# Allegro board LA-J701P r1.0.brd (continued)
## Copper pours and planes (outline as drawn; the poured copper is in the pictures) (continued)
LX1_CPU on BOTTOM: 97.62,103.55 98.5,103.55 98.66,103.4 98.66,102.74 98.81,102.58 98.81,101.29 98.63,101.11 98.63,100.88 98.5,100.75 98.5,99.61 98.43,99.54 98.3,99.54 98.23,99.61 98.23,100.45 98.24,100.46 98.24,100.83 98.38,100.97 98.38,102.18 97.87,102.68 97.69,102.68 97.59,102.79 97.59,103.52
LX1_CPU on IN3: 99.38,104.18 99.64,103.93 99.64,103.43 99.05,102.85 99.05,102.65 98.78,102.38 98.78,101.59 98.66,101.47 98.5,101.47 98.35,101.62 98.35,102.99 98.58,103.22 98.58,104.03 98.73,104.18
LX1_CPU on IN3: 129.34,103.46 130.1,103.46 130.25,103.31 130.25,102.24 130.25,102.23 130.25,101.94 130.06,101.76 129.37,101.76 129.09,102.04 129.09,103.21
LX1_NB on TOP (solid shape): 82.54,99.55 82.54,96.93 82.41,96.8 81.14,96.8 81.04,96.91 81.04,99.6 81.12,99.67 82.41,99.67
LX1_NB on BOTTOM (solid shape): 81.61,104.64 81.61,100.17 83.32,98.47 83.32,95.32 82.93,94.94 81.72,94.94 81.64,95.01 81.64,96.73 80.67,96.73 80.67,95.04 80.57,94.94 78.95,94.94 78.79,95.09 78.79,104.23 79.51,104.95 81.31,104.95
LX1_NB on BOTTOM: 94.85,103.52 95.67,103.52 95.79,103.4 95.79,102.73 96.12,102.41 96.12,102.2 96.33,101.99 96.38,101.99 96.5,101.87 96.5,101.72 96.88,101.34 96.88,99.59 96.82,99.52 96.75,99.52 96.63,99.65 96.63,100.35 96.58,100.39 96.58,101.22 96.28,101.52 96.16,101.52 96.04,101.64 96.04,101.76 95.83,101.97 95.64,101.97 94.72,102.89 94.72,103.4
LX1_NB on IN3: 94.72,103.45 95.51,103.45 95.99,102.96 95.99,102.43 96.5,101.92 96.5,101.67 96.32,101.49 96.22,101.49 94.67,103.04 94.67,103.4
LX1_NB on IN3: 81.09,105.76 81.54,105.76 81.92,105.38 81.92,105.15 81.16,104.39 80.19,104.39 80.08,104.5 80.08,104.74
LX2_CHG on TOP (solid shape): 68.35,11.79 68.35,7.92 68.61,7.66 69.27,7.66 69.35,7.59 69.35,4.13 69.27,4.06 67.36,4.06 67.19,4.23 67.19,5.77 66.95,6.01 65.43,6.01 65.31,6.14 65.31,7.61 65.33,7.63 65.33,12.06 65.65,12.38 67.77,12.38
LX2_CHG on BOTTOM (solid shape): 70.89,11.76 70.89,7.66 69.14,5.91 65.48,5.91 65.31,6.09 65.31,11.42 65.5,11.61 66.89,11.61 67.08,11.8 70.86,11.8
LX2_CHG on BOTTOM (solid shape): 45.04,10.12 45.04,9.36 45.91,8.49 46.73,8.49 46.78,8.44 46.78,8.34 46.73,8.29 45.86,8.29 45.81,8.23 45.26,8.23 44.08,9.41 44.08,10.21 44.13,10.26 44.9,10.26
LX2_CHG on IN3 (solid shape): 67.12,13.42 67.12,12.01 66.95,11.83 66.15,11.83 65.9,12.08 65.9,13.57 66.18,13.85 66.69,13.85
LX2_CHG on IN3 (solid shape): 44.99,10.68 44.99,9.49 45.04,9.43 45.04,9.36 45.52,8.88 45.52,8.52 45.4,8.4 45.39,8.4 44.99,8.4 44.91,8.48 44.87,8.48 44.8,8.5 44.72,8.5 44.19,9.04 44.19,10.82 44.21,10.85 44.82,10.85
LX2_CPU on BOTTOM (solid shape): 117.53,101.72 117.53,94.96 116.01,93.44 113.8,93.44 113.69,93.34 113.69,92.65 113.87,92.47 115.5,92.47 115.78,92.19 115.78,90.52 115.45,90.19 112.91,90.19 112.35,90.75 112.35,95.12 114.86,97.63 114.86,101.62 115.12,101.87 117.38,101.87
LX2_CPU on IN3 (solid shape): 114.14,97.38 114.14,95.45 114.01,95.32 113.3,95.32 113.15,95.47 113.15,97.4 113.3,97.55 113.96,97.55
LX2_CPU on TOP: 115.05,96.58 116.55,96.58 116.75,96.37 116.75,95.05 116.5,94.8 115.05,94.8 114.93,94.93 114.93,96.45
LX2_CPU on BOTTOM: 101.5,103.28 101.5,101.08 100.07,99.65 100.07,99.62 100,99.56 99.93,99.56 99.85,99.64 99.85,100.32 99.93,100.4 100.1,100.4 100.82,101.11 100.82,101.14 100.89,101.21 100.89,101.62 100.38,102.13 100.38,103.24 100.5,103.36 101.43,103.36
LX2_CPU on IN3: 101.32,100.83 100.82,100.32 100.54,100.32 100.38,100.48 100.38,100.65 101.32,101.59 101.5,101.59 102.11,102.2 102.67,102.2 102.8,102.08 102.8,101.49 102.14,100.83
LX3_CPU on TOP (solid shape): 145.66,96.07 145.66,94.52 145.51,94.37 143.42,94.37 143.25,94.54 143.25,95.94 143.48,96.17 145.56,96.17
LX3_CPU on TOP (solid shape): 145.09,104.69 145.09,104.56 145.04,104.51 145.04,104.29 145.24,104.08 145.95,104.08 146.05,103.98 146.05,103.9 145.98,103.83 144.61,103.83 144.48,103.95 144.48,104.74 144.61,104.87 144.91,104.87
LX3_CPU on BOTTOM (solid shape): 145.93,105.15 145.93,104.01 145.77,103.85 144.76,103.85 144.63,103.98 144.63,104.89 144.96,105.22 145.85,105.22
LX3_CPU on BOTTOM (solid shape): 148.11,101.67 148.11,97.71 148.67,97.15 148.67,94.07 148.42,93.82 146.74,93.82 146.28,94.28 146.28,95.24 146.18,95.34 145.34,95.34 145.29,95.29 145.29,94.13 144.96,93.79 143.39,93.79 142.95,94.23 142.95,96.39 143.84,97.27 144.81,97.27 145.37,97.83 145.37,101.85 147.93,101.85
LX3_CPU on IN3 (solid shape): 146.21,98.09 146.21,97.4 145.95,97.15 144.94,97.15 144.75,97.34 144.75,98.13 144.91,98.29 146,98.29
LX3_CPU on IN3 (solid shape): 145.98,104.74 145.98,104.72 146.16,104.54 146.16,103.8 146.08,103.73 144.78,103.73 144.53,103.98 144.53,104.62 144.76,104.84 145.88,104.84
LX_1.8V on TOP (solid shape): 170.81,82.12 170.81,81.41 169.92,80.52 169.66,80.52 167.52,78.38 167.36,78.38 166.72,79.02 166.72,79.23 170.02,82.53 170.4,82.53
LX_1.8V on BOTTOM (solid shape): 170.98,81.92 170.98,81.26 170.17,80.45 170.12,80.45 170.02,80.55 170.02,80.75 170.17,80.9 170.17,82.35 170.25,82.43 170.48,82.43
LX_1.8V on BOTTOM (solid shape): 166.13,80.02 166.34,80.02 166.79,80.47 166.92,80.47 167.2,80.19 167.2,79.69 167.57,79.32 168.81,79.32 169.14,78.99 169.14,78.76 168.08,77.69 168.08,77.68 168.04,77.64 168.04,76.87 167.36,76.19 166.75,76.19 164.7,78.25 164.7,78.57 165.29,79.16 165.29,79.74 164.84,80.19 164.84,80.5 165.09,80.75 165.4,80.75
LX_3V on TOP (solid shape): 175.75,66.57 175.75,66.48 178.48,63.74 178.69,63.74 179.06,64.11 179.29,64.11 179.59,63.81 179.59,63.56 177.52,61.49 176.57,61.49 174.67,63.39 174.67,66.5 175.17,67.01 175.3,67.01
LX_3V on BOTTOM (solid shape): 178.81,67.97 178.81,67.72 180.11,66.41 180.11,65.45 179.18,64.51 179.18,63.82 178.04,62.69 177.49,62.69 175.59,64.58 175.59,64.74 175.03,65.3 175.03,65.63 177.83,68.42 178.36,68.42
LX_3V on TOP: 177.44,68.59 177.79,68.59 178.08,68.29 178.51,68.29 178.65,68.15 178.65,67.95 178.53,67.82 177.21,67.82 177.18,67.85 176.93,67.85 176.85,67.92 176.85,68
LX_5V on TOP (solid shape): 31.61,12.98 32.31,12.98 32.41,12.88 32.41,12.03 32.38,11.99 31.06,11.99 30.34,12.71 30.34,13.57 30.52,13.75 30.85,13.75
LX_5V on BOTTOM (solid shape): 33.96,17.1 34.6,17.1 34.65,17.05 34.65,15.13 34.8,14.98 34.98,14.98 35.08,14.88 37.34,14.88 37.42,14.95 38.13,14.95 38.22,14.86 38.22,14.74 38.15,14.67 37.37,14.67 37.24,14.55 35.33,14.55 35.03,14.24 34.12,14.24 33.39,13.52 33.39,12.83 33.18,12.62 30.69,12.62 30.28,13.02 30.28,14.98 30.99,15.69 30.99,17.11 31.35,17.47 33.6,17.47
LX_DDR on TOP (solid shape): 152.44,41.8 152.44,38.63 152.31,38.5 151.3,38.5 151.11,38.69 151.11,41.74 151.3,41.93 152.31,41.93
LX_DDR on BOTTOM (solid shape): 153.39,42.03 153.65,42.03 153.76,41.92 153.76,41.71 153.74,41.69 153.74,39.93 155.03,38.64 155.03,36.58 154.92,36.47 154.54,36.47 154.22,36.15 152.01,36.15 151.4,36.76 151.4,38.23 150.71,38.92 147.9,38.92 146.96,39.86 146.96,41.13 147.77,41.94 151.65,41.94 151.76,42.04 153.38,42.04
LX_DDR on TOP: 157.93,52.13 158.64,52.13 158.74,52.02 158.74,51.14 158.59,50.98 158.59,50.02 158.44,49.87 157.78,49.87 157.57,50.07 157.57,51.77
LX_DDR on TOP: 152.01,41.89 154.32,41.89 154.6,41.61 154.6,41 154.4,40.8 152.01,40.8 151.86,40.95 151.86,41.74
LX_DDR on BOTTOM: 160.16,54.26 160.21,54.21 160.21,54.13 160.14,54.06 159.53,54.06 158.84,53.37 158.84,51.29 158.64,51.08 158.28,51.08 158.13,51.24 158.13,52.66 158.16,52.68 158.16,53.29 159.12,54.26
LX_VDDP on TOP (solid shape): 161.61,94.29 161.61,94.09 158.94,91.42 158.94,91.32 158.18,90.56 158.08,90.56 157.42,91.22 157.42,91.5 160.65,94.72 161.18,94.72
LX_VDDP on BOTTOM (solid shape): 161.64,94.29 161.64,93.76 160.95,93.07 160.85,93.07 160.75,93.17 160.75,93.58 160.65,93.68 160.65,94.01 161.1,94.47 161.46,94.47
LX_VDDP on BOTTOM (solid shape): 156.95,91.69 158.7,91.69 158.83,91.56 159.19,91.56 159.58,91.17 159.58,91.06 156.54,88.03 156.14,88.03 152.4,91.76 152.4,93.08 153.47,94.15 154.49,94.15
M_BATA on BOTTOM: 80.74,14.76 80.99,14.51 80.99,9.53 80.59,9.12 77.54,9.12 76.19,10.47 73.8,10.47 73.3,10.98 73.3,14.36 73.7,14.76
M_VMB on BOTTOM (solid shape): outline of 91 points within 71.99,4.82 77.45,10.11
Net_14 on BOTTOM (solid shape): 178.53,92.82 170.53,92.82 170.53,100.82 178.53,100.82
REGN on BOTTOM (solid shape): 48.34,12.16 48.34,11.54 48.1,11.3 48.1,11.19 48.08,11.17 48.08,10.27 48.28,10.07 48.28,9.07 48.23,9.02 48.1,9.02 48.05,9.07 48.05,9.84 47.7,10.18 47.7,12.12 47.79,12.21 48.29,12.21
S0I3_EC#_5VEN2 on BOTTOM: 18.65,21.11 18.71,21.05 18.71,20.22 18.58,20.1 16.76,20.1 16.46,20.4 16.46,21.08 16.48,21.11
SNB_APU on TOP (solid shape): 119.1,96.18 120.02,96.18 120.07,96.13 120.07,95.04 119.71,94.68 117.63,94.68 117.43,94.89 117.43,96.49 117.5,96.56 118.72,96.56
SNB_APU2 on TOP (solid shape): 131.19,97.4 131.19,95.88 131.07,95.75 129.21,95.75 129.11,95.85 129.11,96.46 130.13,97.48 131.12,97.48
SNB_APU3 on TOP (solid shape): 148.8,95.45 149.76,95.45 149.89,95.32 149.89,94.58 149.63,94.33 147.2,94.33 147.09,94.43 147.09,95.95 147.25,96.11 148.14,96.11
SNB_APU_NB on TOP (solid shape): 79.71,98.54 79.71,96.97 79.63,96.89 77.52,96.89 77.37,97.05 77.37,97.6 77.45,97.68 78.18,97.68 78.54,98.04 78.54,98.52 78.64,98.62 79.63,98.62
SNB_VDDP on BOTTOM (solid shape): 151.41,92.35 151.41,91.92 152.56,90.77 152.56,90.65 151.84,89.93 151.79,89.93 150.45,91.28 150.45,92.45 150.8,92.8 150.96,92.8
SNUB_1.8V on BOTTOM (solid shape): 164.91,79.33 164.91,79.13 163.92,78.14 163.72,78.14 163.39,78.47 163.39,78.62 163.72,78.95 163.72,79.48 164.07,79.84 164.41,79.84
SNUB_CHG1 on TOP (solid shape): 62.92,5.78 62.92,5.15 63.05,5.02 63.73,5.02 63.81,4.95 63.81,4.21 63.73,4.13 61.7,4.13 61.65,4.18 61.65,5.78 61.74,5.87 62.83,5.87
SNUB_CHG2 on TOP (solid shape): 66.26,5.8 66.26,4.2 66.21,4.15 64.18,4.15 64.1,4.22 64.1,4.96 64.14,5 64.93,5 65.04,5.11 65.04,5.85 65.08,5.89 66.17,5.89
SPK_L1- on BOTTOM (solid shape): 28.79,3.79 28.79,1.91 28.67,1.78 28.17,1.78 28.02,1.94 28.02,2.9 27.6,3.32 27.6,3.83 27.74,3.97 28.62,3.97
SPK_L1- on BOTTOM (solid shape): 15.4,35.27 16.26,35.27 16.39,35.15 16.39,34.79 16.31,34.71 14.56,34.71 13.72,35.55 11.84,35.55 11.81,35.58 11.81,35.73 11.84,35.76 14.91,35.76
SPK_L1- on IN3 (solid shape): 29.98,3.76 29.98,3.28 29.47,2.78 27.57,2.78 27.47,2.88 27.47,3.76 27.7,3.99 29.75,3.99
SPK_L1- on IN3 (solid shape): 20.93,35.58 20.93,35.26 20.62,34.94 20.04,34.94 19.54,35.45 16.87,35.45 16.04,34.63 15.41,34.63 15.22,34.82 15.22,35.2 16.04,36.02 20.49,36.02
SPK_L1-_CONN on BOTTOM (solid shape): 34.26,9.28 34.26,6.69 34.18,6.61 33.24,6.61 33.09,6.76 33.09,9.17 33.28,9.37 34.17,9.37
SPK_L1-_CONN on BOTTOM (solid shape): 29.96,5.26 29.96,4.35 29.89,4.27 26.71,4.27 26.42,3.98 26.42,3.6 27.26,2.76 27.26,1.85 27.19,1.78 26.61,1.78 26.53,1.86 26.53,2.57 26.36,2.75 25.7,2.75 25.64,2.8 25.64,3.92 25.77,4.04 25.77,4.91 25.94,5.07 29.37,5.07 29.66,5.36 29.86,5.36
SPK_L1-_CONN on IN1 (solid shape): 34.31,6.85 34.31,6.46 33.42,5.57 32.97,5.57 32.73,5.82 32.73,6.48 33.3,7.05 34.1,7.05
SPK_L1-_CONN on IN1 (solid shape): 30.88,6.08 30.88,4.7 30.5,4.32 29.71,4.32 29.53,4.5 29.53,4.65 29.3,4.88 29.3,6.18 29.38,6.25 30.7,6.25
SPK_L2+ on BOTTOM (solid shape): 23.16,5.36 23.16,5.12 22.97,4.93 22.97,4.3 22.88,4.22 21.37,4.22 21.3,4.29 21.3,5.34 21.43,5.47 23.05,5.47
SPK_L2+ on BOTTOM (solid shape): 15.37,36.71 16.61,35.88 18.08,35.57 18.39,35.25 18.39,34.24 18.2,34.05 17.68,34.05 16.28,35.45 15.66,35.45 15.08,36.04 14.18,36.04 14,35.86 12.76,35.86 12.66,35.96 11.87,35.96 11.81,36.01 11.81,36.11 11.87,36.16 12.86,36.16 13.13,36.09 13.36,36.25 13.58,36.25 14.04,36.71
SPK_L2+ on IN3 (solid shape): 23.16,6.34 23.16,4.91 22.9,4.65 22.08,4.65 21.89,4.84 21.89,6.3 22.11,6.53 22.97,6.53
SPK_L2+ on IN3 (solid shape): 18.08,35.01 18.08,34.69 18.52,34.24 18.84,34.24 19.03,34.05 19.03,33.42 18.84,33.23 18.39,33.23 17.38,34.24 17.38,35.07 17.44,35.13 17.95,35.13
SPK_L2+_CONN on BOTTOM (solid shape): 35.55,9.23 35.55,6.46 35.73,6.28 35.73,5.23 35.5,5 34.89,5 34.52,5.36 34.52,7.64 34.74,7.85 34.74,9.3 34.84,9.4 35.37,9.4
SPK_L2+_CONN on BOTTOM (solid shape): 24.5,4.88 24.5,2.29 24.32,2.11 21.91,2.11 21.63,2.39 21.63,3.31 21.76,3.43 22.8,3.43 22.85,3.38 22.85,2.88 23,2.72 23.82,2.72 23.89,2.8 23.89,3.82 23.84,3.87 23.44,3.87 23.26,4.04 23.26,4.76 23.54,5.03 24.35,5.03
SPK_L2+_CONN on IN1 (solid shape): 35.77,5.92 35.77,5.16 35.56,4.96 35.54,4.96 34.92,4.34 34.43,4.34 34.12,4.65 34.12,5.01 35.18,6.08 35.61,6.08
SPK_L2+_CONN on IN1 (solid shape): 24.55,4.07 24.55,3.51 24.27,3.22 24.02,3.22 23.16,4.08 23.16,4.13 23.16,4.13 23.16,4.68 23.41,4.93 23.69,4.93
SPK_R1- on BOTTOM (solid shape): 28.41,6.06 29.22,6.06 29.26,6.01 29.26,5.44 29.25,5.44 29.07,5.26 27.88,5.26 27.8,5.34 27.8,6.14 27.94,6.27 28.19,6.27
SPK_R1- on BOTTOM (solid shape): 14.53,34.51 16.79,34.51 16.93,34.37 16.93,34.18 16.36,33.61 16.09,33.61 15.7,34 14.46,34 13.34,35.12 11.87,35.12 11.81,35.17 11.81,35.35 11.84,35.37 13.67,35.37
SPK_R1- on IN3 (solid shape): 28.34,6.13 28.34,5.42 27.63,4.7 27.14,4.7 26.81,5.03 26.81,5.69 27.41,6.29 28.17,6.29
SPK_R1- on IN3 (solid shape): 17,34.44 17,34.12 16.17,33.29 16.17,32.91 15.85,32.59 15.35,32.59 14.77,33.17 15.41,33.8 15.85,33.8 16.62,34.56 16.87,34.56
SPK_R1-_CONN on BOTTOM (solid shape): 36.74,9.2 36.74,6.71 36.59,6.56 36.03,6.56 35.83,6.76 35.83,9.23 35.93,9.33 36.62,9.33
SPK_R1-_CONN on BOTTOM (solid shape): 27.47,8.4 27.47,7.9 26.98,7.41 26.57,7.41 26.38,7.22 26.38,6.91 26.53,6.76 26.99,6.76 27.7,7.47 29.28,7.47 29.35,7.4 29.35,6.89 29.28,6.81 28.01,6.81 27.73,6.53 27.71,6.53 27.61,6.43 27.61,6.28 27.54,6.2 26.15,6.2 25.77,6.58 25.77,7.4 26.2,7.83 26.2,8.27 26.46,8.53 27.35,8.53
SPK_R1-_CONN on IN1 (solid shape): 35.27,7.71 36.17,7.71 36.34,7.55 36.34,6.74 36.14,6.53 35.83,6.53 35.82,6.54 35.09,6.54 34.14,7.49 34.14,8.02 34.41,8.29 34.7,8.29
SPK_R1-_CONN on IN1 (solid shape): 27.99,8.01 29.23,8.01 29.61,7.63 29.61,7.14 29.48,7.02 26.6,7.02 26.25,7.36 26.25,8.32 26.46,8.53 27.47,8.53
SPK_R2+ on BOTTOM (solid shape): 22.14,7.13 23.03,7.13 23.09,7.07 23.09,6.37 22.75,6.03 21.2,6.03 21,6.23 21,7.3 21.2,7.5 21.77,7.5
SPK_R2+ on BOTTOM (solid shape): 14.41,33.85 15.51,33.85 15.85,33.51 16.63,33.51 16.83,33.71 17.36,33.71 17.89,33.19 17.89,32.97 17.76,32.85 15.33,32.85 14.94,33.24 13.97,33.24 13.41,33.8 13.41,34.33 13.01,34.74 11.87,34.74 11.81,34.79 11.81,34.92 11.87,34.97 13.29,34.97
SPK_R2+ on IN3 (solid shape): 18,33.03 18,32.64 17.44,32.09 17.3,32.09 16.74,32.65 16.74,33.43 17.09,33.77 17.25,33.77
SPK_R2+ on IN3 (solid shape): 21.63,7.77 21.63,6.18 21.44,5.99 20.81,5.99 20.62,6.18 20.62,7.83 20.68,7.89 21.5,7.89
SPK_R2+_CONN on BOTTOM (solid shape): 38.09,9.15 38.09,5.59 37.81,5.31 37.28,5.31 37.18,5.42 37.18,9.2 37.33,9.35 37.89,9.35
SPK_R2+_CONN on BOTTOM (solid shape): 23.94,8.51 24.53,8.51 24.54,8.5 24.54,7.43 24.45,7.35 24.45,6.51 24.37,6.43 23.41,6.43 23.21,6.63 23.21,7.37 23.36,7.52 23.54,7.52 23.66,7.4 23.89,7.4 23.94,7.45 23.94,7.8 23.87,7.88 22.24,7.88 22.15,7.97 22.15,8.72 22.36,8.92 23.54,8.92
SPK_R2+_CONN on IN1 (solid shape): 37.66,6.29 37.66,5.25 36.87,4.46 36.48,4.46 36.16,4.78 36.16,5.11 36.55,5.5 36.55,5.87 37.03,6.35 37.6,6.35
SPK_R2+_CONN on IN1 (solid shape): 23.79,7.27 23.79,6.63 23.61,6.46 23.32,6.46 23.31,6.46 23.18,6.48 23.06,6.46 23.05,6.46 22.66,6.46 22.65,6.46 22.52,6.48 22.39,6.46 22.39,6.46 22.14,6.46 21.99,6.61 21.99,7.49 22.06,7.56 23.5,7.56
SYSON on TOP: 193.27,43.9 192.38,43.9 192.32,43.83 192.32,42.18 192.45,42.06 193.53,42.06 193.59,42.12 193.59,43.07 193.34,43.33 193.34,43.83
TYPEC_VIN on TOP (solid shape): 35.28,57.93 35.28,55.24 34.72,54.68 34.25,54.68 34.05,54.88 33.73,54.88 33.51,54.66 33.48,54.63 32.6,54.63 32.47,54.77 32.47,54.93 32.24,55.16 31.93,55.16 31.4,54.63 29.44,54.63 29.12,54.95 29.12,57.63 29.28,57.79 31.56,57.79 31.95,58.18 35.03,58.18
UG1_CPU on BOTTOM: 97.92,102.23 98.17,102.23 98.28,102.13 98.28,101.03 98.1,100.86 98.1,99.61 98.02,99.54 97.92,99.54 97.82,99.64 97.82,102.13
UG1_CPU on BOTTOM: 132.74,102.52 132.74,102.13 132.62,102 131.78,102 131.49,102.29 131.49,103.4 131.64,103.55 132.31,103.55 132.44,103.42 132.44,102.63 132.5,102.57 132.69,102.57
UG1_CPU on IN3: 131.83,104.11 132.46,104.11 132.77,103.8 132.77,102.2 132.54,101.97 131.91,101.97 131.63,102.25 131.63,103.9
UG1_CPU on IN3: 97.64,103.37 98.1,103.37 98.25,103.22 98.25,101.26 98.1,101.11 97.84,101.11 97.44,101.52 97.44,103.17
UG1_CPU_R on BOTTOM (solid shape): 134.12,103.42 134.12,101.47 133.89,101.24 133.4,101.24 133.15,101.49 133.15,102.62 133.15,103.5 133.2,103.55 133.99,103.55
UG1_NB on BOTTOM (solid shape): 95.93,101.68 95.93,101.61 96.14,101.39 96.22,101.39 96.5,101.11 96.5,99.59 96.43,99.52 96.31,99.52 96.24,99.59 96.24,100.68 95.48,101.44 95.48,101.75 95.57,101.83 95.77,101.83
UG1_NB on TOP: 85.7,104.79 85.91,104.59 85.91,103.83 85.6,103.52 84.69,103.52 84.61,103.6 84.61,104.72 84.69,104.79
UG1_NB on IN3: 85.53,104.73 86.97,104.73 87.07,104.63 87.07,103.87 86.95,103.74 85.55,103.74 85.4,103.89 85.4,104.6
UG1_NB on IN3: 94.44,102.3 95.3,102.3 96.37,101.24 96.37,101.08 96.19,100.91 96.04,100.91 95.46,101.49 94.42,101.49 94.24,101.67 94.24,102.1
UG1_NB_R on TOP: 83.8,103.52 82.72,103.52 82.6,103.64 82.6,104.87 82.78,105.05 83.8,105.05 83.86,104.98 83.86,103.59
UG1_NB_R on BOTTOM: 84.51,104.77 84.51,103.88 84.36,103.73 83.49,103.73 82.63,104.59 82.63,104.89 82.78,105.05 84.23,105.05
UG2_CPU on BOTTOM: 100.89,99.28 100.21,99.28 100.16,99.33 100.16,99.46 100.21,99.51 100.46,99.51 101.16,100.21 101.16,100.39 101.32,100.55 101.48,100.55 101.6,100.42 101.6,99.99
UG2_CPU on BOTTOM: 110.68,97.86 111.64,97.86 111.73,97.77 111.73,96.02 111.5,95.79 110.73,95.79 110.61,95.92 110.61,97.78
UG2_CPU on IN3: 110.19,98.8 111.05,98.8 111.95,97.9 111.95,96.93 111.78,96.75 111.09,96.75 110.9,96.94 110.9,97.5 110.02,98.38 110.02,98.63
UG2_CPU on IN3: 101.07,99.56 100.89,99.74 100.89,100.12 101.34,100.56 102.61,100.56 102.73,100.44 102.73,99.85 102.44,99.56
UG2_CPU_R on BOTTOM: 112.2,98.14 112.73,98.14 112.86,98.01 112.86,97.07 112.74,96.96 112.74,95.86 112.55,95.67 112.23,95.67 111.89,96.02 111.89,97.83
UG3_CPU on TOP (solid shape): 146.07,103.54 146.07,103.38 146.02,103.33 145.02,103.33 144.52,102.82 144.31,102.82 143.93,103.21 143.93,103.28 144.26,103.61 145.99,103.61
UG3_CPU_R on TOP (solid shape): 143.54,98.19 143.54,97.66 142.47,96.59 142.09,96.59 141.94,96.74 141.94,97.27 142.56,97.9 142.56,98.21 142.66,98.32 143.41,98.32
UG3_CPU_R on BOTTOM (solid shape): 143.41,98.04 143.41,97.48 142.55,96.61 142.07,96.61 141.94,96.74 141.94,97.22 142.9,98.19 143.26,98.19
UG_DDR on TOP: 152.11,44.81 153.25,44.81 153.46,44.61 153.46,43.08 153.18,42.8 152.29,42.8 151.98,43.11 151.98,44.68
UG_DDR on TOP: 158.11,54.82 158.84,54.82 159.05,54.62 159.05,54.31 157.72,52.99 157.39,52.99 156.94,53.45 156.94,53.65
UG_DDR on BOTTOM: 152.31,42.27 152.19,42.4 152.19,43.62 152.52,43.95 153.31,43.95 153.76,43.49 153.76,42.45 153.58,42.27
UG_DDR on BOTTOM: 160.16,54.67 160.21,54.62 160.21,54.49 160.19,54.46 159.17,54.46 158.46,53.75 158.11,53.75 158.06,53.8 158.06,54.11 158.61,54.67
USBC0_CC1 on TOP (solid shape): 31.35,84.22 31.88,84.22 31.94,84.16 32.66,84.16 32.72,84.22 32.72,83.71 32.67,83.66 31.95,83.66 31.92,83.69 31.91,83.69 31.88,83.71 31.31,83.71 31.03,83.99 30.82,83.99 30.66,84.14 30.66,84.42 30.76,84.52 31.04,84.52
USBC0_CC2 on TOP (solid shape): 31.3,83.58 31.88,83.58 31.96,83.51 32.69,83.51 32.77,83.43 32.77,82.85 32.68,82.76 32.25,82.76 31.88,83.13 31.07,83.13 31.07,83.13 30.86,83.13 30.55,83.44 30.55,83.76 30.68,83.89 30.99,83.89
N27353888 on BOTTOM: 34.64,69.47 35.81,69.47 36.05,69.23 36.05,68.22 35.81,67.98 34.07,67.98 33.98,68.07 33.98,68.98 34.13,69.13 34.3,69.13
N27353922 on BOTTOM (solid shape): 32.49,61.26 32.49,60.37 32.36,60.25 32.15,60.25 31.63,60.77 31.63,61.41 31.69,61.47 32.28,61.47
N27403760 on BOTTOM (solid shape): 24.82,64.85 25.39,64.85 25.45,64.79 25.45,64.03 25.28,63.85 25.28,62.96 25.17,62.86 23.83,62.86 23.6,63.09 23.6,63.77 23.16,64.22 23.16,64.66 23.42,64.92 24.75,64.92
N27479461 on BOTTOM: 161.69,53.85 161.76,53.85 161.81,53.8 161.81,53.02 162.73,52.1 163.57,52.1 164.05,51.62 164.61,51.62 164.68,51.54 164.68,50.75 164.56,50.63 163.9,50.63 163.62,50.91 163.02,50.91 162.74,51.19 161.81,51.19 161.64,51.36 161.64,53.8
N27480057 on TOP: 153.84,40.47 154.8,40.47 155.03,40.24 155.03,37.72 154.83,37.52 154.02,37.52 153.65,37.89 153.65,40.28
N27490635 on TOP (solid shape): 52.07,12.11 52.07,10.94 51.95,10.81 50.57,10.81 50.42,10.97 50.42,12.34 50.5,12.41 51.77,12.41
N27490635 on BOTTOM (solid shape): 52.12,12.34 52.12,10.94 51.36,10.18 51.36,9.6 50.96,9.19 50.96,8.83 50.81,8.68 50.02,8.68 49.99,8.7 49.99,8.83 50.63,9.47 50.63,12.44 50.75,12.57 51.9,12.57
N27490673 on TOP (solid shape): 53.57,11.88 54.18,11.88 54.31,11.75 54.31,11.22 54.05,10.97 52.2,10.97 52.18,10.99 52.18,12.39 52.2,12.41 53.04,12.41
N31049415 on BOTTOM (solid shape): 7.83,40.96 7.83,40.16 8.33,39.65 8.33,38.5 8.26,38.42 8.18,38.42 8.11,38.5 8.11,39.47 7.23,40.35 7.18,40.4 7.18,40.95 7.27,41.04 7.75,41.04
N31049464 on BOTTOM (solid shape): 9,41.72 9,41.17 8.93,41.1 8.64,41.1 8.63,41.1 8.55,41.1 8.36,40.91 8.36,40.17 8.74,39.79 8.74,38.52 8.66,38.45 8.59,38.45 8.51,38.52 8.51,39.67 7.97,40.22 7.97,41.51 8.21,41.75 8.97,41.75
N42640404 on TOP (solid shape): 41.41,82.73 41.41,82.46 41.33,82.39 41.33,81.43 41.19,81.28 41.19,80.81 41.33,80.66 41.33,78.52 41.19,78.38 40.3,78.38 40.06,78.14 39.74,78.14 39.56,78.31 39.56,78.57 39.86,78.86 39.86,79.96 40.65,80.76 40.65,81.65 40.77,81.76 40.77,82.43 40.66,82.54 40.66,82.72 40.65,82.73 40.72,82.8 41.33,82.8
N42774290 on BOTTOM (solid shape): 156.82,93.9 156.82,93.75 156.29,93.22 156.18,93.22 154.92,94.48 154.92,94.63 155.35,95.06 155.65,95.06
N45890946 on BOTTOM (solid shape): 172.08,53.5 172.08,52.98 171.89,52.79 170.74,52.79 170.64,52.69 170.64,52.47 169.89,51.72 169.28,51.72 169.18,51.82 169.18,53.12 169.61,53.55 172.03,53.55

Small or netless copper shapes (teardrops, artwork), in the pictures only: 26 on TOP, 18 on BOTTOM, 1 on IN1, 1 on IN3

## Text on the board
User.Comments: LA-J701P | 2021-01-15 | 2020-01-15 | crazy | FLMA0 | 46.75 | 36.25 | 72.94 | 40.34 | 29.60 | 39.40 | 107.82 | 89.27 | 67.22 | 73.07 | 50.62 | 82.17 | 16.55 | 18.35 | 1.00 | 104.71 | Mark | 3.16 | 0.00 | 96.78 | 93.86 | 0.03 | 46.73 | 47.64 | 67.88 | 35.66 | 52.22 | 55.66 | 64.21 | 14.38 | 94.87 | 105.36 | 92.22 | 110.48 | 94.01 | 102.87 | \U+22057.00 | \U+22056.00 | n | 6.00 | 7.00 | \U+22055.50 | 145.51 | 145.50 | 144.30 | 141.17 | 137.06 | 138.60 | 124.85 | 123.98 | 117.82 | 106.73 | 96.23 | 96.71 | 85.73 | 75.23 | 68.04 | 58.06 | 44.86 | 33.36 | 24.73 | 19.40 | 14.23 | 16.25 | 3.75 | 16.96 | 26.42 | 31.98 | 37.88 | 63.16 | \U+22058.00 | \U+22059.00 | INTEL DIS PCB LIMIT TOP | INTEL_DIS PIN1 TOP VEIW | INTEL DIS PCB WHITE MARK TOP | INTEL DIS PCB PAD TOP | INTEL DIS PCB LIMIT BTM | INTEL DIS PCB PAD BTM | INTEL DIS PCB WHITE MARK BTM
User.44: FIGURE | SIZE | 8.0 | 22.0 | 26.0 | 91.0 | 110.0 | 126.0 | 130.0 | 138.0 | 28.0 | 43.0 | 63.0 | 83.0 | 28.0x18.0 | 39.0x20.0 | 45.0x20.0 | 49.0x26.0 | 63.0x35.0 | 75.0x20.0 | 122.0x83.0 | DRILL CHART: TOP to BOTTOM | ALL UNITS ARE IN MILS | TOLERANCE | +3.0/-3.0 | +2.0/-2.0 | PLATED | NON-PLATED | QTY | 4632 | 19 | 2 | 3 | 1 | 4 | 5
User.45: trace Width | 6.3 | 7.8 | 4.6 | 4 | 5 | 6.5/3.5 | 4.7/3.5 | 4.8/3.5 | 5.3/3.5 | Width/Space | 4.6/4.2 | 5/3.9 | 4/3.5 | 3.5/3.6 | 3.7/3.5 | L2/L4 | L4/L7 | L7 | L2 | IN1 | VCC | IN2 | IN3 | GND2 | BOTTOM | TOP | GND1 | LAYER | NAME | 0.9mm-8L(4mil 50ohm)-TOP G-V IN1 G-V IN2 IN3 G-V Bot-180307.pdf | STACKUP: 8 LAYER | 39 ohm | 50 ohm | 73 ohm | THICKNESS=0.9mm | 80 ohm | 85 ohm | SE50 | 90 ohm | REF | Impedance
